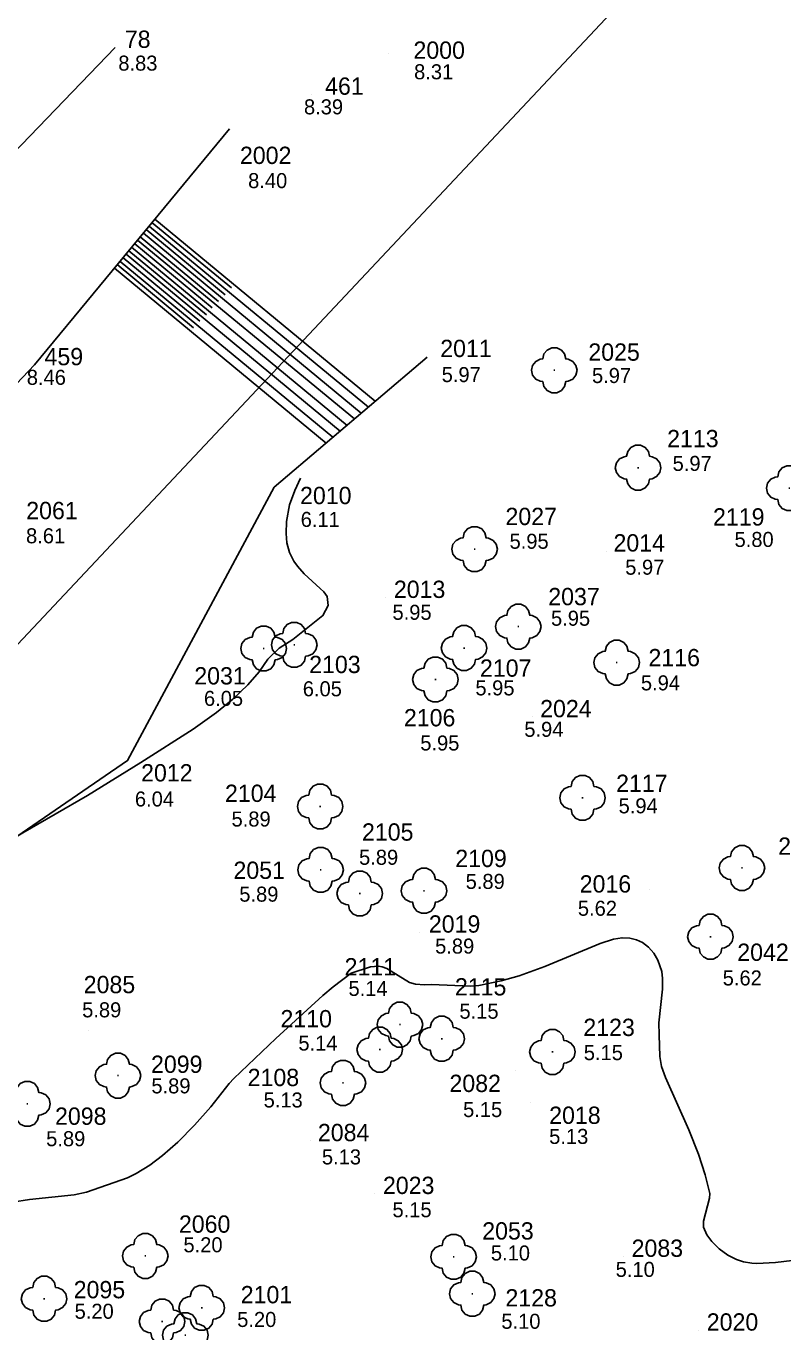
# Model space of a CAD drawing. Extents: x -792549 to -792339, y -1111914 to -1111617.
# Drawn here: x -792428.79 to -792412.17, y -1111708.04 to -1111679.36 of the extents above; entities that cross this region are included whole.
import ezdxf

# ---------------------------------------------------------------- set-up
doc = ezdxf.new("R2010")
doc.units = 0
for name, color, linetype in [('Vrstva 1', 7, 'Continuous'), ('Vrstva 32', 7, 'Continuous'), ('Vrstva 33', 7, 'Continuous'), ('Vrstva 41', 7, 'Continuous'), ('Vrstva 44', 7, 'Continuous'), ('Vrstva 46', 7, 'Continuous'), ('Vrstva 48', 7, 'Continuous'), ('Vrstva 49', 7, 'Continuous'), ('Vrstva 50', 7, 'Continuous'), ('Vrstva 52', 7, 'Continuous'), ('Vrstva 54', 7, 'Continuous')]:
    doc.layers.add(name, color=color, linetype=linetype)

# ---------------------------------------------------------------- blocks, each defined once
blk = doc.blocks.new('SC6231')
at = {"layer": 'Vrstva 1'}
blk.add_line((0, 0), (0, 0), dxfattribs=at)
blk = doc.blocks.new('3$1301')
at = {"layer": 'Vrstva 1'}
for points in [[(20, 0), (19, -4.3), (16.2, -7.8), (12.2, -9.7), (10, -10), (9, -14.3), (6.2, -17.8), (2.2, -19.7), (-2.3, -19.7), (-6.3, -17.8), (-9.1, -14.3), (-10.1, -10), (-12.3, -9.7), (-16.3, -7.8), (-19.1, -4.3), (-20.1, 0), (-19.1, 4.3), (-16.3, 7.8), (-12.3, 9.7), (-10.1, 10), (-9.1, 14.3), (-6.3, 17.8), (-2.3, 19.7), (2.2, 19.7), (6.2, 17.8), (9, 14.3), (10, 10), (12.2, 9.7), (16.2, 7.8), (19, 4.3), (20, 0)], [(-0.5, 0), (0, 0), (0.5, 0)]]:
    blk.add_lwpolyline(points, dxfattribs=at)

msp = doc.modelspace()

# ---------------------------------------------------------------- linework, layer by layer
at = {"layer": 'Vrstva 32'}
for points in [[(-792422.329, -1111691.716), (-792422.684, -1111691.388), (-792422.83, -1111691.22), (-792422.908, -1111691.109), (-792423.003, -1111690.923), (-792423.06, -1111690.71), (-792423.078, -1111690.506), (-792423.067, -1111690.24), (-792423.002, -1111689.874), (-792422.89, -1111689.558), (-792422.764, -1111689.287)], [(-792423.481, -1111693.267), (-792423.228, -1111693.02), (-792422.929, -1111692.831), (-792422.27, -1111692.308), (-792422.159, -1111692.084), (-792422.181, -1111691.89), (-792422.251, -1111691.788), (-792422.329, -1111691.716)], [(-792437.442, -1111705.157), (-792437.323, -1111704.943), (-792436.868, -1111704.252), (-792436.523, -1111703.765), (-792435.841, -1111702.903), (-792435.199, -1111702.148), (-792434.542, -1111701.427), (-792433.862, -1111700.735), (-792433.228, -1111700.131), (-792432.894, -1111699.832), (-792432.339, -1111699.375), (-792431.673, -1111698.871), (-792430.989, -1111698.394), (-792430.157, -1111697.857), (-792428.859, -1111697.079), (-792427.443, -1111696.258), (-792426.27, -1111695.534), (-792425.122, -1111694.804), (-792424.606, -1111694.439), (-792424.247, -1111694.145), (-792423.917, -1111693.825), (-792423.673, -1111693.539), (-792423.481, -1111693.267)]]:
    msp.add_lwpolyline(points, dxfattribs=at)
at = {"layer": 'Vrstva 33'}
for points in [[(-792421.047, -1111700.009), (-792420.967, -1111700.021), (-792420.864, -1111700.06), (-792420.368, -1111700.365), (-792420.239, -1111700.402), (-792420.037, -1111700.413), (-792419.893, -1111700.408), (-792419.021, -1111700.444), (-792418.85, -1111700.433), (-792418.356, -1111700.33), (-792417.964, -1111700.216), (-792417.402, -1111700.013), (-792416.184, -1111699.508), (-792415.891, -1111699.415), (-792415.701, -1111699.381), (-792415.535, -1111699.39), (-792415.384, -1111699.428), (-792415.255, -1111699.489), (-792415.12, -1111699.59), (-792415.007, -1111699.719), (-792414.919, -1111699.872), (-792414.832, -1111700.125), (-792414.813, -1111700.279), (-792414.818, -1111700.513), (-792414.892, -1111701.249), (-792414.89, -1111701.517), (-792414.872, -1111701.992), (-792414.837, -1111702.207), (-792414.752, -1111702.45), (-792414.236, -1111703.603), (-792414.028, -1111704.135), (-792413.879, -1111704.587), (-792413.778, -1111704.996), (-792413.783, -1111705.098), (-792413.918, -1111705.607), (-792413.914, -1111705.739), (-792413.841, -1111705.905), (-792413.735, -1111706.051), (-792413.57, -1111706.213), (-792413.377, -1111706.352), (-792413.192, -1111706.447), (-792413.036, -1111706.5), (-792412.853, -1111706.531), (-792412.745, -1111706.536), (-792412.336, -1111706.516), (-792411.661, -1111706.433)], [(-792422.046, -1111700.462), (-792421.65, -1111700.163), (-792421.223, -1111700.019), (-792421.047, -1111700.009)], [(-792429.085, -1111705.191), (-792428.715, -1111705.131), (-792427.734, -1111705.025), (-792427.463, -1111704.968), (-792426.56, -1111704.652), (-792426.369, -1111704.561), (-792426.07, -1111704.376), (-792425.791, -1111704.166), (-792425.456, -1111703.871), (-792425.087, -1111703.496), (-792424.735, -1111703.097), (-792424.33, -1111702.583), (-792424.225, -1111702.472), (-792423.302, -1111701.597), (-792422.271, -1111700.654), (-792422.046, -1111700.462)]]:
    msp.add_lwpolyline(points, dxfattribs=at)
at = {"layer": 'Vrstva 41'}
msp.add_line((-792456.34, -1111722.07), (-792402.71, -1111664.98), dxfattribs=at)
at = {"layer": 'Vrstva 46'}
for points in [[(-792424.32, -1111681.62), (-792428.6, -1111686.8), (-792432.83, -1111691.26), (-792437.19, -1111695.67), (-792442.24, -1111700.64), (-792446.68, -1111705.3), (-792451.23, -1111709.83), (-792454.32, -1111712.69), (-792456.02, -1111716.09), (-792456.65, -1111719.13), (-792454.6, -1111723.48), (-792450.98, -1111728.02)], [(-792450.34, -1111721.93), (-792450.38, -1111716.93), (-792445.13, -1111710.54), (-792438.2, -1111705.25), (-792433.41, -1111700.19), (-792426.56, -1111695.49), (-792423.34, -1111689.49), (-792419.98, -1111686.63)]]:
    msp.add_lwpolyline(points, dxfattribs=at)
at = {"layer": 'Vrstva 52'}
msp.add_lwpolyline([(-792463.52, -1111716.12), (-792462.35, -1111715.02), (-792457.09, -1111710.06), (-792456.25, -1111709.27), (-792447.6, -1111701.1), (-792439.97, -1111693.46), (-792433.2, -1111686.44), (-792426.83, -1111679.83)], dxfattribs=at)
at = {"layer": 'Vrstva 54'}
for p, q in [((-792426.08, -1111683.76), (-792421.27, -1111687.73)), ((-792426.02, -1111683.68), (-792424.28, -1111685.11)), ((-792425.96, -1111683.6), (-792421.12, -1111687.6)), ((-792426.28, -1111683.99), (-792424.56, -1111685.41)), ((-792426.21, -1111683.91), (-792421.43, -1111687.86)), ((-792426.15, -1111683.83), (-792424.42, -1111685.26)), ((-792426.53, -1111684.3), (-792424.83, -1111685.7)), ((-792426.47, -1111684.22), (-792421.74, -1111688.13)), ((-792426.4, -1111684.14), (-792424.7, -1111685.55)), ((-792426.34, -1111684.06), (-792421.58, -1111687.99)), ((-792426.79, -1111684.6), (-792425.11, -1111685.99)), ((-792426.72, -1111684.53), (-792422.05, -1111688.39)), ((-792426.66, -1111684.45), (-792424.97, -1111685.84)), ((-792426.59, -1111684.37), (-792421.89, -1111688.26)), ((-792426.85, -1111684.68), (-792422.2, -1111688.52))]:
    msp.add_line(p, q, dxfattribs=at)

# ---------------------------------------------------------------- block references
at = {"layer": 'Vrstva 44', "xscale": 0.025, "yscale": 0.025000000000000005}
for p in [(-792417.19, -1111686.92), (-792415.35, -1111689.06), (-792412.03, -1111689.51), (-792418.94, -1111690.85), (-792417.98, -1111692.55), (-792423.57, -1111693.03), (-792422.9, -1111692.95), (-792419.17, -1111693.02), (-792415.82, -1111693.34), (-792419.8, -1111693.71), (-792422.33, -1111696.5), (-792416.57, -1111696.31), (-792422.32, -1111697.89), (-792413.07, -1111697.85), (-792421.46, -1111698.41), (-792420.05, -1111698.35), (-792413.76, -1111699.36), (-792420.58, -1111701.29), (-792419.66, -1111701.6), (-792421.02, -1111701.84), (-792417.23, -1111701.89), (-792426.77, -1111702.41), (-792421.83, -1111702.57), (-792428.76, -1111703.03), (-792426.17, -1111706.37), (-792419.4, -1111706.39), (-792418.99, -1111707.2), (-792428.39, -1111707.31), (-792424.93, -1111707.51), (-792425.8, -1111707.81), (-792425.29, -1111708.11)]:
    msp.add_blockref('3$1301', p, dxfattribs=at)
at = {"layer": 'Vrstva 48', "xscale": 0.1, "yscale": 0.10000000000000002}
for p in [(-792426.83, -1111679.83), (-792420.82, -1111679.96), (-792422.53, -1111680.86), (-792424.32, -1111681.62), (-792419.98, -1111686.63), (-792428.6, -1111686.8), (-792417.19, -1111686.92), (-792415.35, -1111689.06), (-792423.34, -1111689.49), (-792418.94, -1111690.85), (-792416.05, -1111690.9), (-792420.89, -1111691.92), (-792417.98, -1111692.55), (-792423.57, -1111693.03), (-792422.9, -1111692.95), (-792419.17, -1111693.02), (-792415.82, -1111693.34), (-792419.8, -1111693.71), (-792417.66, -1111694.53), (-792426.56, -1111695.49), (-792416.57, -1111696.31), (-792422.33, -1111696.5), (-792422.32, -1111697.89), (-792413.07, -1111697.85), (-792420.05, -1111698.35), (-792415.1, -1111698.32), (-792421.46, -1111698.41), (-792420.14, -1111699.26), (-792413.76, -1111699.36), (-792427.42, -1111701.43), (-792420.58, -1111701.29), (-792419.66, -1111701.6), (-792421.02, -1111701.84), (-792417.23, -1111701.89), (-792418.05, -1111702.3), (-792426.77, -1111702.41), (-792421.83, -1111702.57), (-792428.76, -1111703.03), (-792417.71, -1111703), (-792422.54, -1111703.84), (-792421.13, -1111705), (-792426.17, -1111706.37), (-792419.4, -1111706.39), (-792415.67, -1111706.39), (-792418.99, -1111707.2), (-792428.39, -1111707.31), (-792424.93, -1111707.51), (-792425.8, -1111707.81), (-792414.02, -1111708)]:
    msp.add_blockref('SC6231', p, dxfattribs=at)

# ---------------------------------------------------------------- texts
at = {"layer": 'Vrstva 49'}
for s, p in [('78', (-792426.62, -1111679.84)), ('2000', (-792420.283, -1111680.08)), ('461', (-792422.223, -1111680.87)), ('2002', (-792424.093, -1111682.39)), ('2011', (-792419.695, -1111686.63)), ('2025', (-792416.443, -1111686.71)), ('459', (-792428.383, -1111686.81)), ('2113', (-792414.713, -1111688.61)), ('2010', (-792422.773, -1111689.86)), ('2061', (-792428.785, -1111690.19)), ('2027', (-792418.263, -1111690.32)), ('2119', (-792413.705, -1111690.33)), ('2014', (-792415.891, -1111690.9)), ('2013', (-792420.713, -1111691.92)), ('2037', (-792417.323, -1111692.08)), ('2103', (-792422.573, -1111693.57)), ('2116', (-792415.123, -1111693.42)), ('2031', (-792425.095, -1111693.82)), ('2107', (-792418.823, -1111693.65)), ('2106', (-792420.493, -1111694.74)), ('2024', (-792417.501, -1111694.54)), ('2012', (-792426.263, -1111695.95)), ('2117', (-792415.833, -1111696.18)), ('2104', (-792424.421, -1111696.4)), ('2105', (-792421.413, -1111697.25)), ('2039', (-792412.275, -1111697.56)), ('2109', (-792419.365, -1111697.83)), ('2051', (-792424.235, -1111698.09)), ('2016', (-792416.633, -1111698.39)), ('2019', (-792419.945, -1111699.27)), ('2042', (-792413.173, -1111699.89)), ('2111', (-792421.795, -1111700.21)), ('2085', (-792427.523, -1111700.6)), ('2115', (-792419.373, -1111700.65)), ('2110', (-792423.203, -1111701.35)), ('2123', (-792416.553, -1111701.54)), ('2099', (-792426.045, -1111702.35)), ('2108', (-792423.923, -1111702.64)), ('2082', (-792419.493, -1111702.77)), ('2098', (-792428.153, -1111703.49)), ('2018', (-792417.303, -1111703.47)), ('2084', (-792422.381, -1111703.85)), ('2023', (-792420.953, -1111705.01)), ('2060', (-792425.433, -1111705.86)), ('2053', (-792418.773, -1111706.01)), ('2083', (-792415.493, -1111706.39)), ('2095', (-792427.743, -1111707.3)), ('2101', (-792424.075, -1111707.41)), ('2128', (-792418.263, -1111707.48)), ('2020', (-792413.843, -1111708.01))]:
    msp.add_text(s, height=0.38, dxfattribs=at).set_placement(p)
at = {"layer": 'Vrstva 50'}
for s, p in [('8.83', (-792426.763, -1111680.34)), ('8.31', (-792420.269, -1111680.53)), ('8.39', (-792422.687, -1111681.3)), ('8.40', (-792423.913, -1111682.92)), ('8.46', (-792428.773, -1111687.24)), ('5.97', (-792419.663, -1111687.18)), ('5.97', (-792416.363, -1111687.2)), ('5.97', (-792414.593, -1111689.13)), ('6.11', (-792422.759, -1111690.36)), ('8.61', (-792428.789, -1111690.72)), ('5.95', (-792418.173, -1111690.84)), ('5.80', (-792413.233, -1111690.8)), ('5.97', (-792415.633, -1111691.41)), ('5.95', (-792420.743, -1111692.4)), ('5.95', (-792417.263, -1111692.53)), ('6.05', (-792422.713, -1111694.08)), ('5.95', (-792418.923, -1111694.06)), ('5.94', (-792415.289, -1111693.95)), ('6.05', (-792424.883, -1111694.29)), ('5.94', (-792417.849, -1111694.97)), ('5.95', (-792420.133, -1111695.27)), ('6.04', (-792426.399, -1111696.5)), ('5.94', (-792415.779, -1111696.65)), ('5.89', (-792424.277, -1111696.94)), ('5.89', (-792421.477, -1111697.78)), ('5.89', (-792419.137, -1111698.31)), ('5.89', (-792424.107, -1111698.59)), ('5.62', (-792416.673, -1111698.9)), ('5.89', (-792419.807, -1111699.73)), ('5.62', (-792413.493, -1111700.43)), ('5.14', (-792421.709, -1111700.66)), ('5.89', (-792427.557, -1111701.13)), ('5.15', (-792419.273, -1111701.16)), ('5.14', (-792422.809, -1111701.86)), ('5.15', (-792416.543, -1111702.07)), ('5.89', (-792426.037, -1111702.8)), ('5.13', (-792423.573, -1111703.11)), ('5.15', (-792419.193, -1111703.32)), ('5.89', (-792428.347, -1111703.96)), ('5.13', (-792417.303, -1111703.91)), ('5.13', (-792422.293, -1111704.36)), ('5.15', (-792420.743, -1111705.52)), ('5.20', (-792425.333, -1111706.29)), ('5.10', (-792418.583, -1111706.47)), ('5.10', (-792415.843, -1111706.83)), ('5.20', (-792427.723, -1111707.75)), ('5.20', (-792424.153, -1111707.93)), ('5.10', (-792418.353, -1111707.97))]:
    msp.add_text(s, height=0.33, dxfattribs=at).set_placement(p)

doc.saveas('drawing.dxf')
